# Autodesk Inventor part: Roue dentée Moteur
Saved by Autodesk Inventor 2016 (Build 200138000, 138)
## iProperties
Created: 2013-08
Part Number: Roue dentée Moteur
Material: Générique
Document SubType Name: Modeling
Designer: hilarion
Density: 1 g/cm^3
Appearance: Par défaut
Author: Balduini Gael & Faure Olivier
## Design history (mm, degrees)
node "Roue dentée Moteur1"
node "Roue dentée Moteur"
node "Base1"
